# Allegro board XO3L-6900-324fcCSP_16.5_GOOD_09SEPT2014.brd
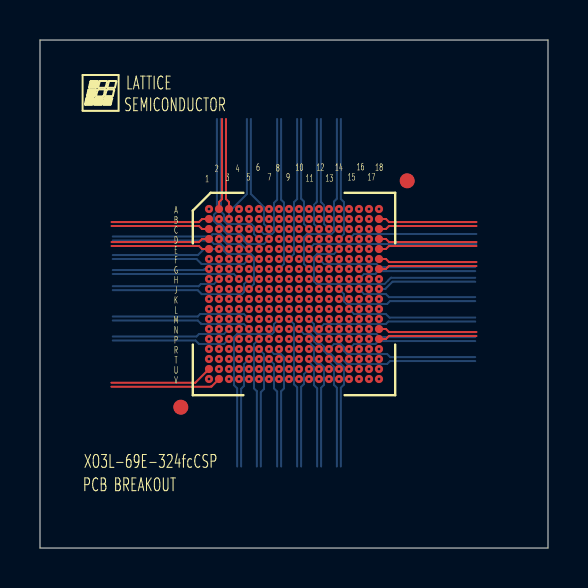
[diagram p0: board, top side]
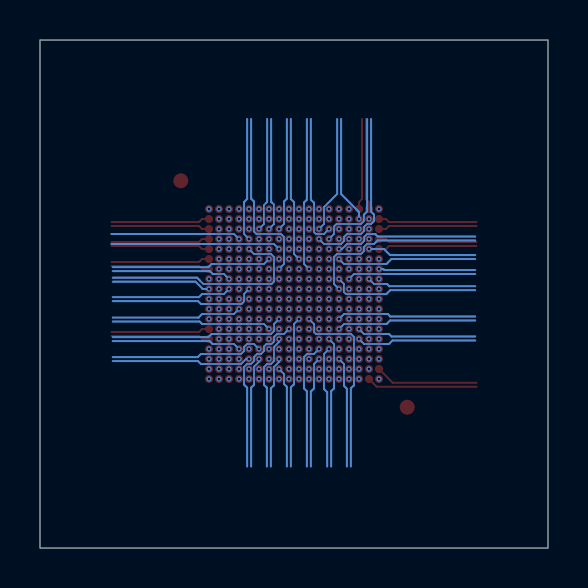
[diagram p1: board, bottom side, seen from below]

Outline 25.4 x 25.4 mm; copper layers: TOP, L2_GND, L3_SIGNAL1, L4_SIGNAL2, L5_GND, L6_SIG3, L5_PWR, BOTTOM. Coordinates in mm from the lower left corner of the outline.
Outline path: 0,25.4 25.4,25.4 25.4,0 0,0 0,25.4

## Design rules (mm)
net group CDPB4: nets PB4C PB4D
net group CDPB6: nets PB6C PB6D
net group CDPB7: nets PB7C PB7D
net group CDPB9: nets PB9C PB9D
net group CDPB13: nets PB13C PB13D
net group CDPB15: nets PB15C PB15D
net group CDPB16: nets PB16C PB16D
net group CDPB18: nets PB18C PB18D
net group CDPB21: nets PB21C PB21D
net group CDPB23: nets PB23C PB23D
net group CDPB26: nets PB26C PB26D
net group CDPB31: nets PB31C PB31D
net group CDPB35: nets PB35C PB35D
net group CDPB37: nets PB37C PB37D
net group CDPB38: nets PB38C PB38D
net group CDPL2: nets PL2C PL2D
net group CDPL3: nets PL3C PL3D
net group CDPL4: nets PL4C PL4D
net group CDPL5: nets PL5C PL5D
net group CDPL6: nets PL6C PL6D
net group CDPL7: nets PL7C PL7D
net group CDPL9: nets PL9C PL9D
net group CDPL10: nets PL10C PL10D
net group CDPL15: nets PL15C PL15D
net group CDPL16: nets PL16C PL16D
net group CDPL18: nets PL18C PL18D
net group CDPL19: nets PL19C PL19D
net group CDPL21: nets PL21C PL21D
net group CDPL23: nets PL23C PL23D
net group CDPL24: nets PL24C PL24D
net group CDPL25: nets PL25C PL25D
net group CDPR2: nets PR2C PR2D
net group CDPR3: nets PR3C PR3D
net group CDPR4: nets PR4C PR4D
net group CDPR6: nets PR6C PR6D
net group CDPR7: nets PR7C PR7D
net group CDPR8: nets PR8C PR8D
net group CDPR10: nets PR10C PR10D
net group CDPR11: nets PR11C PR11D
net group CDPR16: nets PR16C PR16D
net group CDPR17: nets PR17C PR17D
net group CDPR19: nets PR19C PR19D
net group CDPR21: nets PR21C PR21D
net group CDPR22: nets PR22C PR22D
net group CDPR23: nets PR23C PR23D
net group CDPR24: nets PR24C PR24D
net group CDPR25: nets PR25C PR25D
net group CDPT9: nets PT9C PT9D
net group CDPT10: nets PT10C PT10D
net group CDPT11: nets PT11C PT11D
net group CDPT14: nets PT14C PT14D
net group CDPT17: nets PT17C PT17D
net group CDPT18: nets PT18C PT18D
net group CDPT21: nets PT21C PT21D
net group CDPT22: nets PT22C PT22D
net group CDPT25: nets PT25C PT25D
net group CDPT26: nets PT26C PT26D
net group CDPT27: nets PT27C PT27D
net group CDPT33: nets PT33C PT33D
net group CDPT34: nets PT34C PT34D
net group CDPT35: nets PT35C PT35D
net group CDPT36: nets PT36C PT36D
net group DP1: nets PB16A PB16B
net group DP2: nets PB7A PB7B
net group DP3: nets PB13A PB13B
net group DP4: nets PB18A PB18B
net group PB4: nets PB4A PB4B
net group PB6: nets PB6A PB6B
net group PB9: nets PB9A PB9B
net group PB10: nets PB10A PB10B
net group PB12: nets PB12A PB12B
net group PB15: nets PB15A PB15B
net group PB21: nets PB21A PB21B
net group PB23: nets PB23A PB23B
net group PB26: nets PB26A PB26B
net group PB28: nets PB28A PB28B
net group PB29: nets PB29A PB29B
net group PB31: nets PB31A PB31B
net group PB32: nets PB32A PB32B
net group PB34: nets PB34A PB34B
net group PB35: nets PB35A PB35B
net group PB37: nets PB37A PB37B
net group PB38: nets PB38A PB38B
net group PL2: nets PL2A PL2B
net group PL3: nets PL3A PL3B
net group PL4: nets PL4A PL4B
net group PL5: nets PL5A PL5B
net group PL6: nets PL6A PL6B
net group PL8: nets PL8A PL8B
net group PL9: nets PL9A PL9B
net group PL10: nets PL10A PL10B
net group PL11: nets PL11A PL11B
net group PL12: nets PL12A PL12B
net group PL15: nets PL15A PL15B
net group PL17: nets PL17A PL17B
net group PL18: nets PL18A PL18B
net group PL19: nets PL19A PL19B
net group PL22: nets PL22A PL22B
net group PL23: nets PL23A PL23B
net group PL24: nets PL24A PL24B
net group PL25: nets PL25A PL25B
net group PR2: nets PR2A PR2B
net group PR3: nets PR3A PR3B
net group PR4: nets PR4A PR4B
net group PR5: nets PR5A PR5B
net group PR7: nets PR7A PR7B
net group PR8: nets PR8A PR8B
net group PR9: nets PR9A PR9B
net group PR11: nets PR11A PR11B
net group PR12: nets PR12A PR12B
net group PR15: nets PR15A PR15B
net group PR16: nets PR16A PR16B
net group PR17: nets PR17A PR17B
net group PR18: nets PR18A PR18B
net group PR21: nets PR21A PR21B
net group PR22: nets PR22A PR22B
net group PR23: nets PR23A PR23B
net group PR24: nets PR24A PR24B
net group PR25: nets PR25A PR25B
net group PT9: nets PT9A PT9B
net group PT10: nets PT10A PT10B
net group PT11: nets PT11A PT11B
net group PT12: nets PT12A PT12B
net group PT13: nets PT13A PT13B
net group PT14: nets PT14A PT14B
net group PT15: nets PT15A PT15B
net group PT16: nets PT16A PT16B
net group PT17: nets PT17A PT17B
net group PT18: nets PT18A PT18B
net group PT21: nets PT21A PT21B
net group PT22: nets PT22A PT22B
net group PT25: nets PT25A PT25B
net group PT26: nets PT26A PT26B
net group PT27: nets PT27A PT27B
net group PT28: nets PT28A PT28B
net group PT32: nets PT32A PT32B
net group PT33: nets PT33A PT33B
net group PT34: nets PT34A PT34B
net group PT35: nets PT35A PT35B
net group PT36: nets PT36A PT36B

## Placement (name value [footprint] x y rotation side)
BGA  -  [BGA324N50P18X18_1000X1000X10-1]  12.7 12.7 270 top
NOREF  -  []  1.85 21.54 0 top

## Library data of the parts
BGA = BGA324N50P18X18_1000X1000X10-1

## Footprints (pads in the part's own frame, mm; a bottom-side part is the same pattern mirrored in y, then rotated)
BGA324N50P18X18_1000X1000X10-1
  round 0.75 smd: (-5.66,5.66) (5.66,-5.66)
  round 0.406 smd: A1(-4.25,-4.25) A2(-4.25,-3.75) A3(-4.25,-3.25) A4(-4.25,-2.75) A5(-4.25,-2.25) A6(-4.25,-1.75) A7(-4.25,-1.25) A8(-4.25,-0.75) A9(-4.25,-0.25) A10(-4.25,0.25) A11(-4.25,0.75) A12(-4.25,1.25) A13(-4.25,1.75) A14(-4.25,2.25) A15(-4.25,2.75) A16(-4.25,3.25) A17(-4.25,3.75) A18(-4.25,4.25) B1(-3.75,-4.25) B2(-3.75,-3.75) B3(-3.75,-3.25) B4(-3.75,-2.75) B5(-3.75,-2.25) B6(-3.75,-1.75) B7(-3.75,-1.25) B8(-3.75,-0.75) B9(-3.75,-0.25) B10(-3.75,0.25) B11(-3.75,0.75) B12(-3.75,1.25) B13(-3.75,1.75) B14(-3.75,2.25) B15(-3.75,2.75) B16(-3.75,3.25) B17(-3.75,3.75) B18(-3.75,4.25) C1(-3.25,-4.25) C2(-3.25,-3.75) C3(-3.25,-3.25) C4(-3.25,-2.75) C5(-3.25,-2.25) C6(-3.25,-1.75) C7(-3.25,-1.25) C8(-3.25,-0.75) C9(-3.25,-0.25) C10(-3.25,0.25) C11(-3.25,0.75) C12(-3.25,1.25) C13(-3.25,1.75) C14(-3.25,2.25) C15(-3.25,2.75) C16(-3.25,3.25) C17(-3.25,3.75) C18(-3.25,4.25) D1(-2.75,-4.25) D2(-2.75,-3.75) D3(-2.75,-3.25) D4(-2.75,-2.75) D5(-2.75,-2.25) D6(-2.75,-1.75) D7(-2.75,-1.25) D8(-2.75,-0.75) D9(-2.75,-0.25) D10(-2.75,0.25) D11(-2.75,0.75) D12(-2.75,1.25) D13(-2.75,1.75) D14(-2.75,2.25) D15(-2.75,2.75) D16(-2.75,3.25) D17(-2.75,3.75) D18(-2.75,4.25) E1(-2.25,-4.25) E2(-2.25,-3.75) E3(-2.25,-3.25) E4(-2.25,-2.75) E5(-2.25,-2.25) E6(-2.25,-1.75) E7(-2.25,-1.25) E8(-2.25,-0.75) E9(-2.25,-0.25) E10(-2.25,0.25) E11(-2.25,0.75) E12(-2.25,1.25) E13(-2.25,1.75) E14(-2.25,2.25) E15(-2.25,2.75) E16(-2.25,3.25) E17(-2.25,3.75) E18(-2.25,4.25) F1(-1.75,-4.25) F2(-1.75,-3.75) F3(-1.75,-3.25) F4(-1.75,-2.75) F5(-1.75,-2.25) F6(-1.75,-1.75) F7(-1.75,-1.25) F8(-1.75,-0.75) F9(-1.75,-0.25) F10(-1.75,0.25) F11(-1.75,0.75) F12(-1.75,1.25) F13(-1.75,1.75) F14(-1.75,2.25) F15(-1.75,2.75) F16(-1.75,3.25) F17(-1.75,3.75) F18(-1.75,4.25) G1(-1.25,-4.25) G2(-1.25,-3.75) G3(-1.25,-3.25) G4(-1.25,-2.75) G5(-1.25,-2.25) G6(-1.25,-1.75) G7(-1.25,-1.25) G8(-1.25,-0.75) G9(-1.25,-0.25) G10(-1.25,0.25) G11(-1.25,0.75) G12(-1.25,1.25) G13(-1.25,1.75) G14(-1.25,2.25) G15(-1.25,2.75) G16(-1.25,3.25) G17(-1.25,3.75) G18(-1.25,4.25) H1(-0.75,-4.25) H2(-0.75,-3.75) H3(-0.75,-3.25) H4(-0.75,-2.75) H5(-0.75,-2.25) H6(-0.75,-1.75) H7(-0.75,-1.25) H8(-0.75,-0.75) H9(-0.75,-0.25) H10(-0.75,0.25) H11(-0.75,0.75) H12(-0.75,1.25) H13(-0.75,1.75) H14(-0.75,2.25) H15(-0.75,2.75) H16(-0.75,3.25) H17(-0.75,3.75) H18(-0.75,4.25) J1(-0.25,-4.25) J2(-0.25,-3.75) J3(-0.25,-3.25) J4(-0.25,-2.75) J5(-0.25,-2.25) J6(-0.25,-1.75) J7(-0.25,-1.25) J8(-0.25,-0.75) J9(-0.25,-0.25) J10(-0.25,0.25) J11(-0.25,0.75) J12(-0.25,1.25) J13(-0.25,1.75) J14(-0.25,2.25) J15(-0.25,2.75) J16(-0.25,3.25) J17(-0.25,3.75) J18(-0.25,4.25) K1(0.25,-4.25) K2(0.25,-3.75) K3(0.25,-3.25) K4(0.25,-2.75) K5(0.25,-2.25) K6(0.25,-1.75) K7(0.25,-1.25) K8(0.25,-0.75) K9(0.25,-0.25) K10(0.25,0.25) K11(0.25,0.75) K12(0.25,1.25) K13(0.25,1.75) K14(0.25,2.25) K15(0.25,2.75) K16(0.25,3.25) K17(0.25,3.75) K18(0.25,4.25) L1(0.75,-4.25) L2(0.75,-3.75) L3(0.75,-3.25) L4(0.75,-2.75) L5(0.75,-2.25) L6(0.75,-1.75) L7(0.75,-1.25) L8(0.75,-0.75) L9(0.75,-0.25) L10(0.75,0.25) L11(0.75,0.75) L12(0.75,1.25) L13(0.75,1.75) L14(0.75,2.25) L15(0.75,2.75) L16(0.75,3.25) L17(0.75,3.75) L18(0.75,4.25) M1(1.25,-4.25) M2(1.25,-3.75) M3(1.25,-3.25) M4(1.25,-2.75) M5(1.25,-2.25) M6(1.25,-1.75) M7(1.25,-1.25) M8(1.25,-0.75) M9(1.25,-0.25) M10(1.25,0.25) M11(1.25,0.75) M12(1.25,1.25) M13(1.25,1.75) M14(1.25,2.25) M15(1.25,2.75) M16(1.25,3.25) M17(1.25,3.75) M18(1.25,4.25) N1(1.75,-4.25) N2(1.75,-3.75) N3(1.75,-3.25) N4(1.75,-2.75) N5(1.75,-2.25) N6(1.75,-1.75) N7(1.75,-1.25) N8(1.75,-0.75) N9(1.75,-0.25) N10(1.75,0.25) N11(1.75,0.75) N12(1.75,1.25) N13(1.75,1.75) N14(1.75,2.25) N15(1.75,2.75) N16(1.75,3.25) N17(1.75,3.75) N18(1.75,4.25) P1(2.25,-4.25) P2(2.25,-3.75) P3(2.25,-3.25) P4(2.25,-2.75) P5(2.25,-2.25) P6(2.25,-1.75) P7(2.25,-1.25) P8(2.25,-0.75) P9(2.25,-0.25) P10(2.25,0.25) P11(2.25,0.75) P12(2.25,1.25) P13(2.25,1.75) P14(2.25,2.25) P15(2.25,2.75) P16(2.25,3.25) P17(2.25,3.75) P18(2.25,4.25) R1(2.75,-4.25) R2(2.75,-3.75) R3(2.75,-3.25) R4(2.75,-2.75) R5(2.75,-2.25) R6(2.75,-1.75) R7(2.75,-1.25) R8(2.75,-0.75) R9(2.75,-0.25) R10(2.75,0.25) R11(2.75,0.75) R12(2.75,1.25) R13(2.75,1.75) R14(2.75,2.25) R15(2.75,2.75) R16(2.75,3.25) R17(2.75,3.75) R18(2.75,4.25) T1(3.25,-4.25) T2(3.25,-3.75) T3(3.25,-3.25) T4(3.25,-2.75) T5(3.25,-2.25) T6(3.25,-1.75) T7(3.25,-1.25) T8(3.25,-0.75) T9(3.25,-0.25) T10(3.25,0.25) T11(3.25,0.75) T12(3.25,1.25) T13(3.25,1.75) T14(3.25,2.25) T15(3.25,2.75) T16(3.25,3.25) T17(3.25,3.75) T18(3.25,4.25) U1(3.75,-4.25) U2(3.75,-3.75) U3(3.75,-3.25) U4(3.75,-2.75) U5(3.75,-2.25) U6(3.75,-1.75) U7(3.75,-1.25) U8(3.75,-0.75) U9(3.75,-0.25) U10(3.75,0.25) U11(3.75,0.75) U12(3.75,1.25) U13(3.75,1.75) U14(3.75,2.25) U15(3.75,2.75) U16(3.75,3.25) U17(3.75,3.75) U18(3.75,4.25) V1(4.25,-4.25) V2(4.25,-3.75) V3(4.25,-3.25) V4(4.25,-2.75) V5(4.25,-2.25) V6(4.25,-1.75) V7(4.25,-1.25) V8(4.25,-0.75) V9(4.25,-0.25) V10(4.25,0.25) V11(4.25,0.75) V12(4.25,1.25) V13(4.25,1.75) V14(4.25,2.25) V15(4.25,2.75) V16(4.25,3.25) V17(4.25,3.75) V18(4.25,4.25)

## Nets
GND: BGA.A1 BGA.A18 BGA.F6 BGA.F13 BGA.J8 BGA.J9 BGA.J10 BGA.J11 BGA.K8 BGA.K9 BGA.K10 BGA.K11 BGA.N6 BGA.N13 BGA.V1 BGA.V18
VCC: BGA.H7 BGA.H12 BGA.J7 BGA.J12 BGA.K7 BGA.K12 BGA.L7 BGA.L12
VCCIO0: BGA.H8 BGA.H9 BGA.H10 BGA.H11
VCCIO1: BGA.H6 BGA.J6 BGA.K6 BGA.L6
VCCIO2: BGA.L8 BGA.L9 BGA.L10 BGA.L11
VCCIO3: BGA.L13 BGA.M13
VCCIO4: BGA.J13 BGA.K13
VCCIO5: BGA.G13 BGA.H13
PB4A: BGA.R15
PB4B: BGA.M11
PB4C: BGA.N11
PB4D: BGA.T15
PB6A: BGA.V17
PB6B: BGA.R14
PB6C: BGA.V16
PB6D: BGA.U16
PB7A: BGA.V14
PB7B: BGA.U14
PB7C: BGA.V15
PB7D: BGA.U15
PB9A: BGA.N10
PB9B: BGA.T13
PB9C: BGA.T14
PB9D: BGA.R13
PB10A: BGA.V13
PB10B: BGA.M10
PB12A: BGA.P13
PB12B: BGA.P12
PB13A: BGA.U13
PB13B: BGA.U12
PB13C: BGA.R12
PB13D: BGA.T12
PB15A: BGA.P11
PB15B: BGA.T11
PB15C: BGA.N9
PB15D: BGA.V12
PB16A: BGA.R11
PB16B: BGA.V11
PB16C: BGA.U11
PB16D: BGA.M9
PB18A: BGA.P10
PB18B: BGA.R10
PB18C: BGA.U10
PB18D: BGA.T10
PB21A: BGA.V10
PB21B: BGA.P9
PB21C: BGA.U9
PB21D: BGA.V9
PB23A: BGA.T9
PB23B: BGA.T8
PB23C: BGA.R9
PB23D: BGA.V8
PB26A: BGA.U8
PB26B: BGA.V7
PB26C: BGA.R8
PB26D: BGA.P8
PB28A: BGA.R7
PB28B: BGA.T7
PB29A: BGA.N8
PB29B: BGA.U7
PB31A: BGA.U6
PB31B: BGA.V6
PB31C: BGA.R6
PB31D: BGA.P6
PB32A: BGA.P7
PB32B: BGA.T6
PB34A: BGA.T5
PB34B: BGA.M8
PB35A: BGA.U5
PB35B: BGA.U4
PB35C: BGA.V5
PB35D: BGA.N7
PB37A: BGA.V4
PB37B: BGA.R5
PB37C: BGA.U3
PB37D: BGA.V3
PB38A: BGA.U2
PB38B: BGA.T4
PB38C: BGA.V2
PB38D: BGA.U1
PL2A: BGA.D16
PL2B: BGA.E15
PL2C: BGA.C17
PL2D: BGA.D17
PL3A: BGA.B18
PL3B: BGA.C18
PL3C: BGA.G12
PL3D: BGA.E17
PL4A: BGA.D18
PL4B: BGA.E18
PL4C: BGA.F15
PL4D: BGA.F14
PL5A: BGA.E16
PL5B: BGA.F16
PL5C: BGA.F17
PL5D: BGA.G14
PL6A: BGA.F18
PL6B: BGA.G18
PL6C: BGA.G15
PL6D: BGA.H14
PL7C: BGA.H17
PL7D: BGA.H15
PL8A: BGA.G16
PL8B: BGA.G17
PL9A: BGA.H16
PL9B: BGA.F12
PL9C: BGA.H18
PL9D: BGA.J15
PL10A: BGA.J14
PL10B: BGA.J16
PL10C: BGA.E14
PL10D: BGA.J18
PL11A: BGA.J17
PL11B: BGA.K18
PL12A: BGA.K17
PL12B: BGA.K15
PL15A: BGA.K16
PL15B: BGA.K14
PL15C: BGA.L17
PL15D: BGA.L14
PL16C: BGA.N12
PL16D: BGA.L15
PL17A: BGA.L18
PL17B: BGA.L16
PL18A: BGA.M16
PL18B: BGA.M18
PL18C: BGA.N14
PL18D: BGA.M17
PL19A: BGA.M15
PL19B: BGA.N17
PL19C: BGA.N16
PL19D: BGA.N15
PL21C: BGA.M14
PL21D: BGA.M12
PL22A: BGA.N18
PL22B: BGA.P18
PL23A: BGA.P15
PL23B: BGA.P16
PL23C: BGA.P17
PL23D: BGA.R17
PL24A: BGA.R16
PL24B: BGA.R18
PL24C: BGA.T17
PL24D: BGA.P14
PL25A: BGA.T18
PL25B: BGA.U17
PL25C: BGA.U18
PL25D: BGA.T16
PR2A: BGA.B1
PR2B: BGA.C1
PR2C: BGA.C3
PR2D: BGA.C2
PR3A: BGA.D1
PR3B: BGA.E1
PR3C: BGA.G7
PR3D: BGA.D3
PR4A: BGA.D2
PR4B: BGA.E4
PR4C: BGA.E3
PR4D: BGA.F3
PR5A: BGA.E2
PR5B: BGA.F5
PR6C: BGA.F4
PR6D: BGA.F2
PR7A: BGA.G6
PR7B: BGA.F1
PR7C: BGA.G5
PR7D: BGA.G3
PR8A: BGA.G4
PR8B: BGA.G2
PR8C: BGA.G1
PR8D: BGA.H4
PR9A: BGA.H5
PR9B: BGA.H2
PR10C: BGA.H3
PR10D: BGA.H1
PR11A: BGA.E5
PR11B: BGA.J5
PR11C: BGA.J4
PR11D: BGA.J1
PR12A: BGA.J3
PR12B: BGA.J2
PR15A: BGA.K1
PR15B: BGA.K2
PR16A: BGA.K3
PR16B: BGA.K5
PR16C: BGA.K4
PR16D: BGA.L3
PR17A: BGA.L1
PR17B: BGA.L2
PR17C: BGA.L5
PR17D: BGA.L4
PR18A: BGA.M1
PR18B: BGA.M6
PR19C: BGA.M3
PR19D: BGA.M4
PR21A: BGA.M2
PR21B: BGA.N1
PR21C: BGA.N2
PR21D: BGA.N4
PR22A: BGA.M5
PR22B: BGA.N5
PR22C: BGA.N3
PR22D: BGA.P3
PR23A: BGA.P2
PR23B: BGA.P1
PR23C: BGA.R1
PR23D: BGA.P4
PR24A: BGA.R2
PR24B: BGA.R3
PR24C: BGA.R4
PR24D: BGA.M7
PR25A: BGA.T1
PR25B: BGA.T2
PR25C: BGA.P5
PR25D: BGA.T3
PT9A: BGA.B16
PT9B: BGA.B17
PT9C: BGA.A17
PT9D: BGA.B15
PT10A: BGA.C16
PT10B: BGA.A15
PT10C: BGA.C14
PT10D: BGA.A16
PT11A: BGA.F11
PT11B: BGA.C15
PT11C: BGA.E13
PT11D: BGA.B14
PT12A: BGA.D13
PT12B: BGA.A14
PT12C: BGA.D15
PT13A: BGA.G11
PT13B: BGA.D14
PT14A: BGA.A13
PT14B: BGA.D12
PT14C: BGA.B13
PT14D: BGA.F10
PT15A: BGA.C13
PT15B: BGA.C12
PT16A: BGA.E12
PT16B: BGA.A12
PT16C: BGA.E11
PT17A: BGA.F9
PT17B: BGA.C11
PT17C: BGA.G10
PT17D: BGA.B12
PT18A: BGA.E10
PT18B: BGA.B11
PT18C: BGA.D11
PT18D: BGA.G9
PT21A: BGA.B10
PT21B: BGA.C10
PT21C: BGA.A11
PT21D: BGA.D10
PT22A: BGA.A10
PT22B: BGA.D9
PT22C: BGA.A9
PT22D: BGA.B9
PT25A: BGA.C9
PT25B: BGA.E9
PT25C: BGA.B8
PT25D: BGA.A8
PT26A: BGA.D8
PT26B: BGA.F8
PT26C: BGA.C8
PT26D: BGA.E8
PT27A: BGA.C7
PT27B: BGA.B3
PT27C: BGA.A7
PT27D: BGA.B7
PT28A: BGA.A6
PT28B: BGA.E7
PT32A: BGA.D7
PT32B: BGA.D6
PT33A: BGA.G8
PT33B: BGA.C6
PT33C: BGA.B5
PT33D: BGA.B6
PT34A: BGA.A4
PT34B: BGA.E6
PT34C: BGA.F7
PT34D: BGA.A5
PT35A: BGA.D4
PT35B: BGA.C5
PT35C: BGA.D5
PT35D: BGA.B2
PT36A: BGA.A3
PT36B: BGA.A2
PT36C: BGA.C4
PT36D: BGA.B4

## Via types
v1: diameter 0.254, hole 0.152, TOP to BOTTOM, 308 vias

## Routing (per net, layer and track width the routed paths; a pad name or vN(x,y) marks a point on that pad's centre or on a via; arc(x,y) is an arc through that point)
GND:
  vias: v1(8.45,16.95) v1(8.45,8.45) v1(10.95,14.45) v1(10.95,10.95) v1(11.95,12.95) v1(11.95,12.45) v1(12.45,12.95) v1(12.45,12.45) v1(12.95,12.95) v1(12.95,12.45) v1(13.45,12.95) v1(13.45,12.45) v1(14.45,14.45) v1(14.45,10.95) v1(16.95,16.95) v1(16.95,8.45)
VCC:
  vias: v1(11.45,13.45) v1(11.45,12.95) v1(11.45,12.45) v1(11.45,11.95) v1(13.95,13.45) v1(13.95,12.95) v1(13.95,12.45) v1(13.95,11.95)
VCCIO0:
  vias: v1(11.95,13.45) v1(12.45,13.45) v1(12.95,13.45) v1(13.45,13.45)
VCCIO1:
  vias: v1(10.95,13.45) v1(10.95,12.95) v1(10.95,12.45) v1(10.95,11.95)
VCCIO2:
  vias: v1(11.95,11.95) v1(12.45,11.95) v1(12.95,11.95) v1(13.45,11.95)
VCCIO3:
  vias: v1(14.45,11.95) v1(14.45,11.45)
VCCIO4:
  vias: v1(14.45,12.95) v1(14.45,12.45)
VCCIO5:
  vias: v1(14.45,13.95) v1(14.45,13.45)
PB4A: length 6.5
  BOTTOM w0.089: v1(15.45,9.95) 15.7,10.2 16.64,10.2
  BOTTOM w0.102: 16.64,10.2 16.77,10.2 16.92,10.35 21.76,10.35
PB4B: length 8.9
  BOTTOM w0.089: 16.51,10.7 13.85,10.7 13.7,10.85 13.7,11.2 v1(13.45,11.45)
  BOTTOM w0.102: 16.51,10.7 16.82,10.7 16.98,10.54 21.76,10.54
PB4C: length 8.4
  L6_SIG3 w0.089: 14.7,8.29 14.7,9.05 14.55,9.2 13.33,9.2 13.2,9.33 13.2,10.7 v1(13.45,10.95)
  L6_SIG3 w0.102: 14.7,8.29 14.7,8.14 14.82,8.01 14.82,4.08
PB4D: length 5.5
  L6_SIG3 w0.089: 15.2,8.26 15.2,9.2 15.45,9.45 v1(15.45,9.45)
  L6_SIG3 w0.102: 15.02,4.08 15.02,8.04 15.2,8.22 15.2,8.26
PB6A: length 4.5
  L3_SIGNAL1 w0.102: v1(16.45,8.45) 16.45,8.2 16.76,7.89 16.76,4.08
PB6B: length 7
  L3_SIGNAL1 w0.089: 16.2,8.26 16.2,9.05 16.05,9.2 15.35,9.2 15.2,9.35 15.2,9.7 v1(14.95,9.95)
  L3_SIGNAL1 w0.102: 16.2,8.26 16.2,8.17 16.37,7.99 16.38,7.99 16.56,7.81 16.56,4.08
PB6C: length 4.4
  L3_SIGNAL1 w0.102: v1(15.95,8.45) 15.9,8.4 15.9,8.08 16.02,7.95 16.02,4.08
PB6D: length 5
  L3_SIGNAL1 w0.089: v1(15.95,8.95) 15.7,8.7 15.7,8.23
  L3_SIGNAL1 w0.102: 15.7,8.23 15.7,7.99 15.82,7.87 15.82,4.08
PB7A: length 4.5
  L4_SIGNAL2 w0.102: 15.26,4.08 15.26,7.69 14.95,8 v1(14.95,8.45)
PB7B: length 5.1
  L4_SIGNAL2 w0.089: v1(14.95,8.95) 15.2,8.7 15.2,8.33
  L4_SIGNAL2 w0.102: 15.46,4.08 15.46,7.78 15.2,8.03 15.2,8.33
PB7C: length 4.5
  L3_SIGNAL1 w0.102: v1(15.45,8.45) 15.4,8.4 15.4,8.12 15.1,7.82 15.1,4.08
PB7D: length 5.1
  L3_SIGNAL1 w0.089: v1(15.45,8.95) 15.2,8.7 15.2,8.42
  L3_SIGNAL1 w0.102: 14.9,4.08 14.9,7.9 15.2,8.2 15.2,8.42
PB9A: length 8.5
  BOTTOM w0.089: 15.2,8.29 15.2,9.05 15.05,9.2 14.85,9.2 14.7,9.35 14.7,9.55 14.55,9.7 14.35,9.7 14.2,9.85 14.2,10.08 14.08,10.2 13.83,10.2 13.7,10.33 13.7,10.55 13.55,10.7 13.2,10.7 v1(12.95,10.95)
  BOTTOM w0.102: 15.2,8.29 15.2,8.17 15.04,8.01 15.04,4.08
PB9B: length 5.5
  BOTTOM w0.089: v1(14.45,9.45) 14.45,9.32 14.7,9.07 14.7,8.23
  BOTTOM w0.102: 14.7,8.23 14.7,8.16 14.85,8.01 14.85,4.08
PB9C: length 7
  BOTTOM w0.089: v1(14.95,9.45) 15.1,9.45 15.35,9.2 17.07,9.2
  BOTTOM w0.102: 21.76,9.35 17.5,9.35 17.35,9.2 17.07,9.2
PB9D: length 7.8
  BOTTOM w0.089: 17.14,9.7 15.35,9.7 15.2,9.85 15.2,10.05 15.05,10.2 14.7,10.2 v1(14.45,9.95)
  BOTTOM w0.102: 17.14,9.7 17.36,9.7 17.51,9.54 21.76,9.54
PB10A: length 4.4
  L4_SIGNAL2 w0.102: 14.63,4.08 14.63,7.66 14.5,7.79 14.5,8.15 14.45,8.2 v1(14.45,8.45)
PB10B: length 8.9
  L4_SIGNAL2 w0.089: 14.7,8.35 14.7,11.06 14.56,11.2 13.2,11.2 v1(12.95,11.45)
  L4_SIGNAL2 w0.102: 14.82,4.08 14.82,7.74 14.7,7.87 14.7,8.35
PB12A: length 7.5
  L6_SIG3 w0.089: 16.66,10.63 16.58,10.7 14.7,10.7 v1(14.45,10.45)
  L6_SIG3 w0.102: 21.82,10.55 16.73,10.55 16.66,10.63
PB12B: length 8
  L6_SIG3 w0.089: v1(13.95,10.45) 14.2,10.2 16.67,10.2 16.73,10.26
  L6_SIG3 w0.102: 16.73,10.26 16.82,10.36 21.82,10.36
PB13A: length 5
  L6_SIG3 w0.089: v1(14.45,8.95) 14.2,8.7 14.2,8.39
  L6_SIG3 w0.102: 14.2,8.39 14.2,8.23 14.05,8.09 14.05,4.08
PB13B: length 5
  L6_SIG3 w0.089: v1(13.95,8.95) 13.82,8.82 13.82,8.81 13.7,8.69 13.7,8.39
  L6_SIG3 w0.102: 13.7,8.39 13.7,8.22 13.86,8.06 13.86,4.08
PB13C: length 6.5
  L3_SIGNAL1 w0.089: 14.7,8.33 14.7,9.55 14.55,9.7 14.35,9.7 14.2,9.7 v1(13.95,9.95)
  L3_SIGNAL1 w0.102: 14.51,4.08 14.51,7.98 14.7,8.17 14.7,8.33
PB13D: length 5.5
  L3_SIGNAL1 w0.089: 14.2,8.26 14.2,9.2 v1(13.95,9.45)
  L3_SIGNAL1 w0.102: 14.2,8.26 14.2,8.14 14.31,8.02 14.31,4.08
PB15A: length 6.9
  BOTTOM w0.089: 14.2,8.35 14.2,8.52 14.2,9.05 14.05,9.2 13.85,9.2 13.7,9.35 13.7,10.05 13.45,10.3 v1(13.45,10.45)
  BOTTOM w0.102: 14.05,4.08 14.05,8.01 14.2,8.16 14.2,8.35
PB15B: length 5.5
  BOTTOM w0.089: v1(13.45,9.45) 13.45,9.3 13.7,9.05 13.7,8.3
  BOTTOM w0.102: 13.86,4.08 13.86,7.98 13.7,8.14 13.7,8.3
PB15C: length 8.4
  L4_SIGNAL2 w0.089: 14.2,8.55 14.2,10.01 14.2,10.56 14.06,10.7 12.7,10.7 v1(12.45,10.95)
  L4_SIGNAL2 w0.102: 14.21,4.08 14.21,7.95 14.2,7.96 14.2,8.35 14.2,8.55
PB15D: length 4.4
  L4_SIGNAL2 w0.102: 14.01,4.08 14.01,7.86 13.95,7.93 v1(13.95,8.45)
PB16A: length 6
  L4_SIGNAL2 w0.089: 13.71,7.96 13.7,7.96 13.7,9.7 v1(13.45,9.95)
  L4_SIGNAL2 w0.102: 13.71,4.08 13.71,7.96
PB16B: length 4.4
  L4_SIGNAL2 w0.102: v1(13.45,8.45) 13.45,8.01 13.51,7.96 13.51,4.08
PB16C: length 5
  BOTTOM w0.089: v1(13.45,8.95) 13.2,8.7 13.2,8.36
  BOTTOM w0.102: 13.2,8.36 13.2,8.2 13.05,8.06 13.05,4.08
PB16D: length 7.5
  BOTTOM w0.089: 12.7,8.29 12.7,11.2 v1(12.45,11.45)
  BOTTOM w0.102: 12.86,4.08 12.86,8.03 12.7,8.19 12.7,8.29
PB18A: length 7
  L3_SIGNAL1 w0.089: v1(12.95,10.45) 13.2,10.2 13.55,10.2 13.7,10.05 13.7,8.33
  L3_SIGNAL1 w0.102: 13.52,4.08 13.52,7.99 13.7,8.17 13.7,8.33
PB18B: length 6
  L3_SIGNAL1 w0.089: v1(12.95,9.95) 13.2,9.7 13.2,8.36
  L3_SIGNAL1 w0.102: 13.2,8.36 13.2,8.11 13.32,7.98 13.32,4.08
PB18C: length 5
  L6_SIG3 w0.089: 13.2,8.36 13.2,8.7 v1(12.95,8.95)
  L6_SIG3 w0.102: 13.2,8.36 13.2,8.14 13.05,7.99 13.05,4.08
PB18D: length 5.5
  L6_SIG3 w0.089: v1(12.95,9.45) 12.7,9.2 12.7,8.36
  L6_SIG3 w0.102: 12.7,8.36 12.7,8.11 12.86,7.95 12.86,4.08
PB21A: length 4.4
  L4_SIGNAL2 w0.102: 13,4.08 13,7.96 12.95,8.01 v1(12.95,8.45)
PB21B: length 6.9
  L4_SIGNAL2 w0.089: v1(12.45,10.45) 12.7,10.2 13.05,10.2 13.2,10.05 13.2,8.26
  L4_SIGNAL2 w0.102: 13.2,4.08 13.2,8.26
PB21C: length 5
  L4_SIGNAL2 w0.089: 12.71,8.14 12.71,8.69 v1(12.45,8.95)
  L4_SIGNAL2 w0.102: 12.71,4.08 12.71,8.14
PB21D: length 4.4
  L4_SIGNAL2 w0.102: v1(12.45,8.45) 12.45,8.01 12.51,7.96 12.51,4.08
PB23A: length 5.5
  L6_SIG3 w0.089: 12.2,8.23 12.2,9.2 v1(12.45,9.45)
  L6_SIG3 w0.102: 12.2,8.23 12.2,8.08 12.05,7.93 12.05,4.08
PB23B: length 5.5
  L6_SIG3 w0.089: 11.7,8.26 11.7,9.2 v1(11.95,9.45)
  L6_SIG3 w0.102: 11.7,8.26 11.7,8.11 11.86,7.95 11.86,4.08
PB23C: length 6
  L4_SIGNAL2 w0.089: 12.2,8.24 12.2,9.7 v1(12.45,9.95)
  L4_SIGNAL2 w0.102: 12.2,4.08 12.2,8.24
PB23D: length 4.4
  L4_SIGNAL2 w0.102: 12,4.08 12,7.95 11.95,8 v1(11.95,8.45)
PB26A: length 5
  L3_SIGNAL1 w0.089: 11.71,8.21 11.71,8.71 v1(11.95,8.95)
  L3_SIGNAL1 w0.102: 11.7,4.08 11.7,5.04 11.71,5.04 11.71,8.21
PB26B: length 4.4
  L3_SIGNAL1 w0.102: 11.5,4.08 11.5,5.04 11.5,5.04 11.5,8.12 11.45,8.17 v1(11.45,8.45)
PB26C: length 6.1
  L3_SIGNAL1 w0.089: v1(11.95,9.95) 12.2,9.7 12.2,8.33
  L3_SIGNAL1 w0.102: 12.38,4.08 12.38,7.93 12.2,8.11 12.2,8.33
PB26D: length 6.9
  L3_SIGNAL1 w0.089: 12.7,8.39 12.7,10.05 12.55,10.2 12.2,10.2 v1(11.95,10.45)
  L3_SIGNAL1 w0.102: 12.58,4.08 12.58,7.98 12.7,8.11 12.7,8.39
PB28A: length 6.5
  BOTTOM w0.089: v1(11.45,9.95) 11.7,9.7 12.05,9.7 12.2,9.55 12.2,8.36
  BOTTOM w0.102: 12.2,8.36 12.2,7.98 12.05,7.84 12.05,4.08
PB28B: length 5.5
  BOTTOM w0.089: 11.7,8.33 11.7,9.2 v1(11.45,9.45)
  BOTTOM w0.102: 11.7,8.33 11.7,7.98 11.86,7.83 11.86,4.08
PB29A: length 7.8
  L6_SIG3 w0.089: v1(11.95,10.95) 11.7,10.7 11.35,10.7 11.2,10.55 11.2,9.35 11.05,9.2 10.85,9.2 10.7,9.05 10.7,8.36
  L6_SIG3 w0.102: 10.7,8.36 10.7,8.17 10.85,8.02 10.85,4.08
PB29B: length 5
  L6_SIG3 w0.089: 11.2,8.35 11.2,8.7 v1(11.45,8.95)
  L6_SIG3 w0.102: 11.2,8.35 11.2,8.23 11.04,8.08 11.04,4.08
PB31A: length 5
  L3_SIGNAL1 w0.089: v1(10.95,8.95) 11.21,8.69 11.21,8.24
  L3_SIGNAL1 w0.102: 11.21,8.24 11.21,8.17 11.13,8.09 11.13,4.08
PB31B: length 4.4
  L3_SIGNAL1 w0.102: 10.93,4.08 10.93,8.17 11,8.24 11,8.4 v1(10.95,8.45)
PB31C: length 6
  BOTTOM w0.089: 11.2,8.3 11.2,9.7 v1(10.95,9.95)
  BOTTOM w0.102: 11.04,4.08 11.04,7.79 11.2,7.95 11.2,8.3
PB31D: length 6.5
  BOTTOM w0.089: v1(10.95,10.45) 10.7,10.2 10.7,8.29
  BOTTOM w0.102: 10.7,8.29 10.7,7.98 10.84,7.84 10.84,4.08
PB32A: length 6.5
  L4_SIGNAL2 w0.089: v1(11.45,10.45) 11.7,10.2 11.7,8.38
  L4_SIGNAL2 w0.102: 11.52,4.08 11.52,8.08 11.7,8.25 11.7,8.38
PB32B: length 5.5
  L4_SIGNAL2 w0.089: 11.2,8.36 11.2,9.2 v1(10.95,9.45)
  L4_SIGNAL2 w0.102: 11.2,8.36 11.2,8.2 11.33,8.08 11.33,4.08
PB34A: length 5.5
  BOTTOM w0.089: v1(10.45,9.45) 10.2,9.2 10.2,9.05 10.2,8.55 10.2,8.33
  BOTTOM w0.102: 10.06,4.08 10.06,7.96 10.2,8.11 10.2,8.33
PB34B: length 9.4
  BOTTOM w0.089: 9.7,8.35 9.7,10.55 9.85,10.7 11.61,10.7 11.69,10.79 11.69,11.19 v1(11.95,11.45)
  BOTTOM w0.102: 9.7,8.35 9.7,8.14 9.86,7.98 9.86,4.08
PB35A: length 5
  L4_SIGNAL2 w0.089: 10.7,8.33 10.7,8.7 v1(10.45,8.95)
  L4_SIGNAL2 w0.102: 10.7,8.33 10.7,8.14 10.55,7.99 10.55,4.08
PB35B: length 5
  L4_SIGNAL2 w0.089: v1(9.95,8.95) 10.2,8.7 10.2,8.29
  L4_SIGNAL2 w0.102: 10.36,4.08 10.36,8 10.2,8.15 10.2,8.29
PB35C: length 4.4
  L3_SIGNAL1 w0.102: 10.33,4.08 10.33,7.93 10.45,8.06 v1(10.45,8.45)
PB35D: length 7.5
  L3_SIGNAL1 w0.089: v1(11.45,10.95) 11.3,10.8 11.29,10.8 11.2,10.7 10.85,10.7 10.7,10.55 10.7,10.35 10.7,9.85 10.7,9.35 10.7,8.85 10.7,8.55
  L3_SIGNAL1 w0.102: 10.52,4.08 10.52,7.85 10.7,8.03 10.7,8.35 10.7,8.55
PB37A: length 4.4
  L4_SIGNAL2 w0.102: v1(9.95,8.45) 9.95,8.14 9.9,8.09 9.9,4.09
PB37B: length 6.4
  L4_SIGNAL2 w0.089: v1(10.45,9.95) 10.19,9.69 9.85,9.69 9.7,9.54 9.7,8.26
  L4_SIGNAL2 w0.102: 9.7,4.09 9.7,8.26
PB37C: length 5.1
  L3_SIGNAL1 w0.102: v1(9.45,8.95) 9.2,8.7 9.2,7.98 8.9,7.69 8.9,4.08
PB37D: length 4.5
  L3_SIGNAL1 w0.102: v1(9.45,8.45) 9.45,7.95 9.1,7.61 9.1,4.08
PB38A: length 5.9
  L3_SIGNAL1 w0.089: 9.7,8.36 9.7,8.85 9.7,9.06 9.56,9.2 9.2,9.2 v1(8.95,8.95)
  L3_SIGNAL1 w0.102: 9.7,8.36 9.7,8.08 9.81,7.96 9.81,4.08
PB38B: length 5.6
  L3_SIGNAL1 w0.089: 10.2,8.29 10.2,9.2 v1(9.95,9.45)
  L3_SIGNAL1 w0.102: 10.2,8.29 10.2,8.17 10.01,7.98 10.01,4.08
PB38C: length 5.5
  TOP w0.102: BGA.V2 8.57,8.07 3.58,8.07
PB38D: length 5.2
  TOP w0.102: 3.58,8.26 7.76,8.26 BGA.U1
PL2A: length 6
  L6_SIG3 w0.089: 16.73,15.64 16.67,15.7 16.2,15.7 v1(15.95,15.45)
  L6_SIG3 w0.102: 16.73,15.64 16.79,15.58 21.82,15.58
PL2B: length 6.5
  L6_SIG3 w0.089: v1(15.45,14.95) 15.6,14.95 15.85,15.2 15.95,15.2 16.54,15.2 16.55,15.21 16.67,15.32
  L6_SIG3 w0.102: 16.67,15.32 16.72,15.38 21.82,15.38
PL2C: length 5.4
  L3_SIGNAL1 w0.102: v1(16.45,15.95) 16.6,15.8 21.82,15.8
PL2D: length 5.4
  L3_SIGNAL1 w0.102: v1(16.45,15.45) 16.6,15.6 21.82,15.6
PL3A: length 4.9
  TOP w0.102: 21.82,16.3 17.45,16.3 17.3,16.45 BGA.B18
PL3B: length 4.9
  TOP w0.102: BGA.C18 17.3,15.95 17.45,16.1 21.82,16.1
PL3C: length 8.4
  L6_SIG3 w0.089: v1(13.95,13.95) 14.2,14.2 14.55,14.2 14.7,14.35 14.7,14.57 14.83,14.7 16.64,14.7
  L6_SIG3 w0.102: 21.82,14.81 16.91,14.81 16.79,14.7 16.64,14.7
PL3D: length 5.4
  L6_SIG3 w0.102: 21.82,15.01 16.82,15.01 16.76,14.95 v1(16.45,14.95)
PL4A: length 4.9
  TOP w0.102: 21.82,15.3 17.45,15.3 17.3,15.45 BGA.D18
PL4B: length 4.9
  TOP w0.102: BGA.E18 17.3,14.95 17.45,15.1 21.82,15.1
PL4C: length 6.5
  L4_SIGNAL2 w0.089: v1(15.45,14.45) 15.7,14.7 16.61,14.7
  L4_SIGNAL2 w0.102: 16.61,14.7 16.79,14.7 16.92,14.82 21.82,14.82
PL4D: length 7.5
  L4_SIGNAL2 w0.089: 16.61,15.2 15.35,15.2 15.2,15.05 15.2,14.7 v1(14.95,14.45)
  L4_SIGNAL2 w0.102: 16.61,15.2 16.76,15.2 16.94,15.02 21.82,15.02
PL5A: length 6
  L3_SIGNAL1 w0.089: v1(15.95,14.95) 16.2,15.2 16.64,15.2
  L3_SIGNAL1 w0.102: 16.64,15.2 16.84,15.2 17.02,15.02 21.82,15.02
PL5B: length 6
  L3_SIGNAL1 w0.089: 16.67,14.7 16.2,14.7 v1(15.95,14.45)
  L3_SIGNAL1 w0.102: 21.82,14.82 17.01,14.82 16.89,14.7 16.67,14.7
PL5C: length 5.4
  L6_SIG3 w0.102: v1(16.45,14.45) 17.07,14.45 17.2,14.32 21.82,14.32
PL5D: length 7
  L6_SIG3 w0.089: 16.67,14.2 15.2,14.2 v1(14.95,13.95)
  L6_SIG3 w0.102: 16.67,14.2 17.04,14.2 17.12,14.13 21.82,14.13
PL6A: length 4.9
  TOP w0.102: 21.82,14.3 17.45,14.3 17.3,14.45 BGA.F18
PL6B: length 4.9
  TOP w0.102: BGA.G18 17.3,13.95 17.45,14.1 21.82,14.1
PL6C: length 6.5
  L4_SIGNAL2 w0.089: v1(15.45,13.95) 15.7,14.2 16.67,14.2
  L4_SIGNAL2 w0.102: 21.82,14.09 16.86,14.09 16.75,14.2 16.67,14.2
PL6D: length 7.1
  L4_SIGNAL2 w0.089: v1(14.95,13.45) 15.2,13.7 16.63,13.7 16.76,13.83
  L4_SIGNAL2 w0.102: 21.82,13.89 16.82,13.89 16.76,13.83
PL7C: length 5.5
  L3_SIGNAL1 w0.102: 21.82,13.59 17.38,13.59 17.26,13.7 16.7,13.7 v1(16.45,13.45)
PL7D: length 6.6
  L3_SIGNAL1 w0.089: v1(15.45,13.45) 15.7,13.2 17.11,13.2
  L3_SIGNAL1 w0.102: 17.11,13.2 17.2,13.2 17.39,13.39 21.82,13.39
PL8A: length 6.1
  L3_SIGNAL1 w0.089: 16.7,14.2 16.2,14.2 v1(15.95,13.95)
  L3_SIGNAL1 w0.102: 16.7,14.2 17.05,14.2 17.36,14.5 21.82,14.5
PL8B: length 5.5
  L3_SIGNAL1 w0.102: v1(16.45,13.95) 17.08,13.95 17.44,14.3 21.82,14.3
PL9A: length 6
  BOTTOM w0.089: v1(15.95,13.45) 16.2,13.7 16.61,13.7
  BOTTOM w0.102: 16.61,13.7 16.76,13.7 16.91,13.85 21.76,13.85
PL9B: length 8
  BOTTOM w0.089: 16.68,14.2 14.2,14.2 v1(13.95,14.45)
  BOTTOM w0.102: 21.76,14.04 16.98,14.04 16.82,14.2 16.68,14.2
PL9C: length 5
  L6_SIG3 w0.102: v1(16.95,13.45) 16.95,13.45 17.14,13.64 21.82,13.64
PL9D: length 6.9
  L6_SIG3 w0.089: 16.78,13.75 16.73,13.7 15.85,13.7 15.7,13.55 15.7,13.2 v1(15.45,12.95)
  L6_SIG3 w0.102: 21.82,13.84 16.87,13.84 16.78,13.75
PL10A: length 7.4
  BOTTOM w0.089: 17.07,12.2 15.32,12.2 15.2,12.33 15.2,12.7 v1(14.95,12.95)
  BOTTOM w0.102: 21.76,12.35 17.5,12.35 17.36,12.2 17.07,12.2
PL10B: length 6
  BOTTOM w0.089: v1(15.95,12.95) 16.2,12.7 17.11,12.7
  BOTTOM w0.102: 17.11,12.7 17.29,12.7 17.45,12.54 21.76,12.54
PL10C: length 10.9
  BOTTOM w0.089: v1(14.95,14.95) 14.7,14.7 13.85,14.7 13.7,14.55 13.7,13.32 13.82,13.2 17.23,13.2 17.4,13.37
  BOTTOM w0.102: 21.76,13.51 17.54,13.51 17.4,13.37
PL10D: length 5
  BOTTOM w0.102: 21.76,13.31 17.63,13.31 17.26,12.95 v1(16.95,12.95)
PL11A: length 5.5
  L3_SIGNAL1 w0.089: v1(16.45,12.95) 16.7,12.7 17.51,12.7
  L3_SIGNAL1 w0.102: 21.82,12.7 17.51,12.7
PL11B: length 4.9
  L3_SIGNAL1 w0.102: v1(16.95,12.45) 17.43,12.45 17.48,12.5 21.82,12.5
PL12A: length 5.5
  L6_SIG3 w0.089: v1(16.45,12.45) 16.69,12.69 17.19,12.69 17.25,12.75
  L6_SIG3 w0.102: 21.82,12.82 17.32,12.82 17.25,12.75
PL12B: length 6.9
  L6_SIG3 w0.089: v1(15.45,12.45) 15.7,12.7 16.05,12.7 16.2,12.85 16.2,13.05 16.35,13.2 17.15,13.2 17.24,13.11
  L6_SIG3 w0.102: 17.24,13.11 17.32,13.02 21.82,13.02
PL15A: length 6
  L4_SIGNAL2 w0.089: 17.14,12.7 16.2,12.7 v1(15.95,12.45)
  L4_SIGNAL2 w0.102: 21.82,12.86 17.48,12.86 17.32,12.7 17.14,12.7
PL15B: length 7.4
  L4_SIGNAL2 w0.089: 17.17,13.2 15.35,13.2 15.2,13.05 15.2,12.7 v1(14.95,12.45)
  L4_SIGNAL2 w0.102: 17.17,13.2 17.39,13.2 17.53,13.06 21.82,13.06
PL15C: length 5.5
  L6_SIG3 w0.089: 17.2,12.14 17.13,12.21 16.71,12.21 v1(16.45,11.95)
  L6_SIG3 w0.102: 21.82,12.04 17.29,12.04 17.2,12.14
PL15D: length 7
  L6_SIG3 w0.089: 17.07,11.7 15.2,11.7 v1(14.95,11.95)
  L6_SIG3 w0.102: 21.82,11.85 17.34,11.85 17.2,11.7 17.07,11.7
PL16C: length 8
  BOTTOM w0.089: v1(13.95,10.95) 14.2,11.2 14.55,11.2 15.05,11.2 15.55,11.2 17.14,11.2
  BOTTOM w0.102: 21.76,11.32 17.41,11.32 17.29,11.2 17.14,11.2
PL16D: length 6.5
  BOTTOM w0.089: 17.17,11.7 15.7,11.7 v1(15.45,11.95)
  BOTTOM w0.102: 21.76,11.52 17.47,11.52 17.29,11.7 17.17,11.7
PL17A: length 4.9
  L3_SIGNAL1 w0.102: v1(16.95,11.95) 17.26,11.95 17.31,12 21.82,12
PL17B: length 6
  L3_SIGNAL1 w0.089: 17.13,12.2 16.2,12.2 v1(15.95,11.95)
  L3_SIGNAL1 w0.102: 21.82,12.2 17.13,12.2
PL18A: length 6
  L3_SIGNAL1 w0.089: 17.05,11.71 16.21,11.71 v1(15.95,11.45)
  L3_SIGNAL1 w0.102: 21.82,11.71 17.05,11.71
PL18B: length 4.9
  L3_SIGNAL1 w0.102: 21.82,11.51 17.39,11.51 17.34,11.45 v1(16.95,11.45)
PL18C: length 7.1
  L6_SIG3 w0.089: v1(14.95,10.95) 15.2,11.2 16.39,11.2 16.39,11.2 16.55,11.2 16.87,10.89
  L6_SIG3 w0.102: 21.82,10.89 16.87,10.89
PL18D: length 5.5
  L6_SIG3 w0.089: v1(16.45,11.45) 16.58,11.45 16.95,11.09
  L6_SIG3 w0.102: 21.82,11.09 16.95,11.09
PL19A: length 6.5
  L3_SIGNAL1 w0.089: v1(15.45,11.45) 15.7,11.2 16.64,11.2
  L3_SIGNAL1 w0.102: 16.64,11.2 16.82,11.2 17,11.02 21.82,11.02
PL19B: length 5.4
  L3_SIGNAL1 w0.102: 21.82,10.83 16.92,10.83 16.79,10.95 v1(16.45,10.95)
PL19C: length 6
  L4_SIGNAL2 w0.089: 16.76,11.2 16.2,11.2 v1(15.95,10.95)
  L4_SIGNAL2 w0.102: 16.76,11.2 16.93,11.03 21.82,11.03
PL19D: length 6.5
  L4_SIGNAL2 w0.089: v1(15.45,10.95) 15.7,10.7 16.66,10.7
  L4_SIGNAL2 w0.102: 21.82,10.83 16.96,10.83 16.82,10.7 16.66,10.7
PL21C: length 7
  L4_SIGNAL2 w0.089: 17.14,11.7 15.2,11.7 v1(14.95,11.45)
  L4_SIGNAL2 w0.102: 21.82,11.85 17.41,11.85 17.26,11.7 17.14,11.7
PL21D: length 8.5
  L4_SIGNAL2 w0.089: v1(13.95,11.45) 14.2,11.7 14.2,12.05 14.35,12.2 17.1,12.2
  L4_SIGNAL2 w0.102: 17.1,12.2 17.32,12.2 17.48,12.05 21.82,12.05
PL22A: length 4.9
  TOP w0.102: 21.82,10.8 17.45,10.8 17.3,10.95 BGA.N18
PL22B: length 4.9
  TOP w0.102: BGA.P18 17.3,10.45 17.45,10.6 21.82,10.6
PL23A: length 6.5
  L3_SIGNAL1 w0.089: 16.64,10.2 15.7,10.2 v1(15.45,10.45)
  L3_SIGNAL1 w0.102: 16.64,10.2 16.73,10.2 16.88,10.35 21.82,10.35
PL23B: length 6
  L3_SIGNAL1 w0.089: 16.54,10.7 16.2,10.7 v1(15.95,10.45)
  L3_SIGNAL1 w0.102: 16.54,10.7 16.67,10.7 16.82,10.54 21.82,10.54
PL23C: length 5.5
  L4_SIGNAL2 w0.102: 21.82,10.55 17.1,10.55 16.95,10.4 16.5,10.4 v1(16.45,10.45)
PL23D: length 5.5
  L4_SIGNAL2 w0.102: v1(16.45,9.95) 16.7,10.2 17.03,10.2 17.18,10.35 21.82,10.35
PL24A: length 6
  L3_SIGNAL1 w0.089: v1(15.95,9.95) 16.19,9.71 17.26,9.71
  L3_SIGNAL1 w0.102: 21.82,9.71 17.26,9.71
PL24B: length 4.9
  L3_SIGNAL1 w0.102: 21.82,9.9 17.31,9.9 17.26,9.95 v1(16.95,9.95)
PL24C: length 5.5
  L4_SIGNAL2 w0.089: 16.2,8.36 16.2,9.2 v1(16.45,9.45)
  L4_SIGNAL2 w0.102: 16.2,8.36 16.2,8.25 16.05,8.1 16.05,4.08
PL24D: length 6.9
  L4_SIGNAL2 w0.089: 15.7,8.39 15.7,10.04 15.54,10.21 15.19,10.21 v1(14.95,10.45)
  L4_SIGNAL2 w0.102: 15.86,4.08 15.86,8.08 15.7,8.23 15.7,8.39
PL25A: length 5
  L3_SIGNAL1 w0.102: v1(16.95,9.45) 17.3,9.1 21.82,9.1
PL25B: length 5.6
  L3_SIGNAL1 w0.089: v1(16.45,8.95) 16.7,8.7 17.13,8.7 17.21,8.78
  L3_SIGNAL1 w0.102: 17.21,8.78 17.33,8.9 21.82,8.9
PL25C: length 5
  L4_SIGNAL2 w0.102: v1(16.95,8.95) 17.31,9.31 21.82,9.31
PL25D: length 6.1
  L4_SIGNAL2 w0.089: v1(15.95,9.45) 16.2,9.7 17.07,9.7
  L4_SIGNAL2 w0.102: 17.07,9.7 17.2,9.7 17.39,9.51 21.82,9.51
PR2A: length 4.9
  TOP w0.102: 3.58,16.3 7.95,16.3 8.1,16.45 BGA.B1
PR2B: length 4.9
  TOP w0.102: 3.58,16.1 7.95,16.1 8.1,15.95 BGA.C1
PR2C: length 6.1
  L3_SIGNAL1 w0.089: v1(9.45,15.95) 9.2,16.2 8.76,16.2
  L3_SIGNAL1 w0.102: 3.58,16.44 8.05,16.44 8.06,16.46 8.23,16.46 8.48,16.2 8.76,16.2
PR2D: length 5.5
  L3_SIGNAL1 w0.102: 3.58,16.24 8.13,16.24 8.14,16.26 8.45,15.95 v1(8.95,15.95)
PR3A: length 4.9
  TOP w0.102: BGA.D1 8.1,15.45 7.95,15.3 3.58,15.3
PR3B: length 4.9
  TOP w0.102: 3.58,15.1 7.95,15.1 8.1,14.95 BGA.E1
PR3C: length 8.4
  L4_SIGNAL2 w0.089: v1(11.45,13.95) 11.2,14.2 11.2,14.55 11.05,14.7 8.83,14.7
  L4_SIGNAL2 w0.102: 8.83,14.7 8.67,14.7 8.49,14.88 3.64,14.88
PR3D: length 6
  L4_SIGNAL2 w0.089: v1(9.45,15.45) 9.2,15.2 8.7,15.2 8.65,15.15
  L4_SIGNAL2 w0.102: 8.65,15.15 8.58,15.07 3.64,15.07
PR4A: length 5.4
  L3_SIGNAL1 w0.089: v1(8.95,15.45) 8.58,15.45 8.53,15.51 3.58,15.51
PR4B: length 6.8
  L3_SIGNAL1 w0.089: 3.58,15.69 8.61,15.69 ; v1(9.95,14.95) 9.7,15.2 9.35,15.2 9.2,15.35 9.2,15.55 9.05,15.7 8.7,15.7
  L3_SIGNAL1 w0.102: 8.61,15.69 8.62,15.7 8.7,15.7
PR4C: length 6
  L6_SIG3 w0.089: v1(9.45,14.95) 9.2,15.2 8.73,15.2
  L6_SIG3 w0.102: 3.58,15.06 8.45,15.06 8.6,15.2 8.73,15.2
PR4D: length 6
  L6_SIG3 w0.089: v1(9.45,14.45) 9.2,14.7 8.76,14.7
  L6_SIG3 w0.102: 3.58,14.86 8.39,14.86 8.54,14.7 8.76,14.7
PR5A: length 5.4
  BOTTOM w0.102: 3.64,14.65 7.9,14.65 8.2,14.95 v1(8.95,14.95)
PR5B: length 7
  BOTTOM w0.089: v1(10.45,14.45) 10.2,14.2 8.26,14.2
  BOTTOM w0.102: 8.26,14.2 8.08,14.2 7.83,14.45 3.64,14.45
PR6C: length 6.9
  L4_SIGNAL2 w0.089: v1(9.95,14.45) 9.69,14.19 9.69,13.85 9.54,13.7 8.26,13.7
  L4_SIGNAL2 w0.102: 3.64,13.86 7.95,13.86 8.11,13.7 8.26,13.7
PR6D: length 5.5
  L4_SIGNAL2 w0.089: v1(8.95,14.45) 8.69,14.19 8.29,14.19
  L4_SIGNAL2 w0.102: 3.64,14.06 8.01,14.06 8.15,14.19 8.29,14.19
PR7A: length 8
  L3_SIGNAL1 w0.089: 8.54,14.88 8.72,14.7 9.05,14.7 9.55,14.7 10.05,14.7 10.55,14.7 10.7,14.55 10.7,14.2 v1(10.95,13.95)
  L3_SIGNAL1 w0.102: 3.58,15.02 8.4,15.02 8.54,14.88
PR7B: length 5.2
  L3_SIGNAL1 w0.102: v1(8.45,14.45) 8.45,14.69 8.32,14.82 3.58,14.82
PR7C: length 7
  L6_SIG3 w0.089: 8.23,13.76 8.29,13.7 10.2,13.7 v1(10.45,13.95)
  L6_SIG3 w0.102: 3.58,13.84 8.15,13.84 8.23,13.76
PR7D: length 6
  L6_SIG3 w0.089: v1(9.45,13.95) 9.2,14.2 8.31,14.2 8.23,14.12
  L6_SIG3 w0.102: 3.58,14.04 8.15,14.04 8.23,14.12
PR8A: length 6.5
  L3_SIGNAL1 w0.089: v1(9.95,13.95) 9.7,14.2 9.35,14.2 8.23,14.2
  L3_SIGNAL1 w0.102: 3.58,14.03 7.9,14.03 8.08,14.2 8.23,14.2
PR8B: length 5.5
  L3_SIGNAL1 w0.089: 8.3,13.7 8.7,13.7 v1(8.95,13.95)
  L3_SIGNAL1 w0.102: 8.3,13.7 8.08,13.7 7.95,13.83 3.58,13.83
PR8C: length 4.8
  BOTTOM w0.102: 3.64,13.9 8.18,13.9 8.24,13.95 v1(8.45,13.95)
PR8D: length 6.4
  BOTTOM w0.089: 8.24,13.7 9.7,13.7 v1(9.95,13.45)
  BOTTOM w0.102: 3.64,13.7 8.24,13.7
PR9A: length 7.4
  BOTTOM w0.089: v1(10.45,13.45) 10.21,13.21 10.21,12.8 10.1,12.69 8.29,12.69
  BOTTOM w0.102: 3.64,12.89 7.88,12.89 8.08,12.69 8.29,12.69
PR9B: length 5.5
  BOTTOM w0.089: v1(8.95,13.45) 8.7,13.2 8.23,13.2
  BOTTOM w0.102: 8.23,13.2 8.04,13.2 7.94,13.09 3.64,13.09
PR10C: length 6
  L3_SIGNAL1 w0.089: v1(9.45,13.45) 9.2,13.2 8.23,13.2
  L3_SIGNAL1 w0.102: 3.58,13.06 7.78,13.06 7.92,13.2 8.23,13.2
PR10D: length 5
  L3_SIGNAL1 w0.102: v1(8.45,13.45) 7.89,13.45 7.7,13.26 3.58,13.26
PR11A: length 7.3
  BOTTOM w0.089: 8.79,15.69 9.05,15.69 9.19,15.55 9.19,15.35 9.35,15.2 10.05,15.2 10.3,14.95 v1(10.45,14.95)
  BOTTOM w0.102: 3.64,15.57 8.51,15.57 8.63,15.69 8.79,15.69
PR11B: length 9.2
  BOTTOM w0.089: 8.62,15.28 8.7,15.2 9.05,15.2 9.2,15.05 9.2,14.85 9.35,14.7 10.55,14.7 10.7,14.55 10.7,13.2 v1(10.45,12.95)
  BOTTOM w0.102: 8.62,15.28 8.52,15.38 3.64,15.38
PR11C: length 6.4
  L4_SIGNAL2 w0.089: v1(9.95,12.95) 9.7,13.2 8.31,13.2
  L4_SIGNAL2 w0.102: 3.64,13.2 8.31,13.2
PR11D: length 4.8
  L4_SIGNAL2 w0.102: v1(8.45,12.95) 8.13,12.95 8.08,13 3.64,13
PR12A: length 6
  L6_SIG3 w0.089: v1(9.45,12.95) 9.2,12.7 8.26,12.7 8.17,12.79
  L6_SIG3 w0.102: 8.17,12.79 8.1,12.86 3.58,12.86
PR12B: length 5.5
  L6_SIG3 w0.089: 8.24,13.21 8.69,13.21 v1(8.95,12.95)
  L6_SIG3 w0.102: 8.24,13.21 8.18,13.21 8.03,13.06 3.58,13.06
PR15A: length 4.9
  L3_SIGNAL1 w0.102: v1(8.45,12.45) 8.04,12.45 7.99,12.5 3.58,12.5
PR15B: length 5.5
  L3_SIGNAL1 w0.089: 8.17,12.7 8.7,12.7 v1(8.95,12.45)
  L3_SIGNAL1 w0.102: 3.58,12.7 8.17,12.7
PR16A: length 6
  L4_SIGNAL2 w0.089: 8.23,12.2 9.2,12.2 v1(9.45,12.45)
  L4_SIGNAL2 w0.102: 8.23,12.2 8.1,12.2 7.95,12.35 3.64,12.35
PR16B: length 7
  L4_SIGNAL2 w0.089: v1(10.45,12.45) 10.2,12.7 8.26,12.7
  L4_SIGNAL2 w0.102: 8.26,12.7 8.11,12.7 7.95,12.55 3.64,12.55
PR16C: length 7.4
  L4_SIGNAL2 w0.089: v1(9.95,12.45) 9.7,12.2 9.7,11.35 9.55,11.2 8.61,11.2 8.29,11.2
  L4_SIGNAL2 w0.102: 8.29,11.2 8.05,11.2 7.9,11.34 3.64,11.34
PR16D: length 6
  L4_SIGNAL2 w0.089: v1(9.45,11.95) 9.2,11.7 8.29,11.7
  L4_SIGNAL2 w0.102: 8.29,11.7 8.08,11.7 7.91,11.54 3.64,11.54
PR17A: length 4.9
  L3_SIGNAL1 w0.102: 3.58,11.78 6.74,11.78 6.92,11.95 8.45,11.95 v1(8.45,11.95)
PR17B: length 5.6
  L3_SIGNAL1 w0.089: v1(8.95,11.95) 8.7,12.2 8.2,12.2
  L3_SIGNAL1 w0.102: 3.58,11.97 6.66,11.97 6.89,12.2 8.2,12.2
PR17C: length 7
  L6_SIG3 w0.089: 8.33,12.2 10.2,12.2 v1(10.45,11.95)
  L6_SIG3 w0.102: 8.33,12.2 8.11,12.2 7.98,12.08 3.58,12.08
PR17D: length 6.5
  L6_SIG3 w0.089: v1(9.95,11.95) 9.7,11.7 8.29,11.7
  L6_SIG3 w0.102: 3.58,11.88 7.9,11.88 8.08,11.7 8.29,11.7
PR18A: length 5
  L3_SIGNAL1 w0.102: v1(8.45,11.45) 8.04,11.45 7.99,11.5 7.09,11.5 6.78,11.2 3.58,11.2
PR18B: length 7.6
  L3_SIGNAL1 w0.089: 8.26,11.7 10.7,11.7 v1(10.95,11.45)
  L3_SIGNAL1 w0.102: 8.26,11.7 7,11.7 6.7,11.4 3.58,11.4
PR19C: length 6
  L6_SIG3 w0.089: v1(9.45,11.45) 9.2,11.2 8.3,11.2
  L6_SIG3 w0.102: 3.58,11.08 8.04,11.08 8.17,11.2 8.3,11.2
PR19D: length 7
  L6_SIG3 w0.089: v1(9.95,11.45) 9.7,11.2 9.7,10.85 9.55,10.7 8.26,10.7
  L6_SIG3 w0.102: 3.58,10.88 7.99,10.88 8.17,10.7 8.26,10.7
PR21A: length 5.6
  L3_SIGNAL1 w0.089: v1(8.95,11.45) 8.7,11.2 8.35,11.2
  L3_SIGNAL1 w0.102: 8.35,11.2 8.09,11.2 8.04,11.15 7.12,11.15 6.81,10.84 3.58,10.84
PR21B: length 5
  L3_SIGNAL1 w0.102: 3.58,10.64 6.89,10.64 7.2,10.95 8.04,10.95 8.14,10.95 8.14,10.95 8.45,10.95 v1(8.45,10.95)
PR21C: length 5.5
  L4_SIGNAL2 w0.089: v1(8.95,10.95) 8.7,10.7 8.29,10.7
  L4_SIGNAL2 w0.102: 3.64,10.55 7.99,10.55 8.14,10.7 8.29,10.7
PR21D: length 6.9
  L4_SIGNAL2 w0.089: 8.36,10.2 9.55,10.2 9.7,10.35 9.7,10.7 v1(9.95,10.95)
  L4_SIGNAL2 w0.102: 3.64,10.35 7.98,10.35 8.13,10.2 8.36,10.2
PR22A: length 7
  BOTTOM w0.089: v1(10.45,11.45) 10.2,11.7 8.26,11.7
  BOTTOM w0.102: 3.64,11.58 7.89,11.58 8.01,11.7 8.26,11.7
PR22B: length 7
  BOTTOM w0.089: 8.2,11.2 8.85,11.2 10.2,11.2 v1(10.45,10.95)
  BOTTOM w0.102: 3.64,11.38 7.89,11.38 8.07,11.2 8.2,11.2
PR22C: length 6
  BOTTOM w0.089: v1(9.45,10.95) 9.2,10.7 8.26,10.7
  BOTTOM w0.102: 3.64,10.58 7.83,10.58 7.95,10.7 8.26,10.7
PR22D: length 6
  BOTTOM w0.089: v1(9.45,10.45) 9.2,10.2 8.23,10.2
  BOTTOM w0.102: 8.23,10.2 7.95,10.2 7.77,10.38 3.64,10.38
PR23A: length 5.7
  L3_SIGNAL1 w0.089: 8.29,10.7 8.7,10.7 8.76,10.64 8.76,10.64 v1(8.95,10.45)
  L3_SIGNAL1 w0.102: 3.58,10.25 6.88,10.25 7.33,10.7 8.29,10.7
PR23B: length 5
  L3_SIGNAL1 w0.102: 3.58,10.05 6.96,10.05 7.36,10.45 8.45,10.45 v1(8.45,10.45)
PR23C: length 5.1
  L3_SIGNAL1 w0.102: v1(8.45,9.95) 8.45,9.95 8.2,9.95 8.15,10 7.66,10 7.11,9.45 3.58,9.45
PR23D: length 6.7
  L3_SIGNAL1 w0.089: v1(9.95,10.45) 9.83,10.33 9.82,10.33 9.7,10.2 8.23,10.2
  L3_SIGNAL1 w0.102: 8.23,10.2 7.58,10.2 7.02,9.65 3.58,9.65
PR24A: length 5.5
  L4_SIGNAL2 w0.089: v1(8.95,9.95) 8.7,9.7 8.24,9.7
  L4_SIGNAL2 w0.102: 3.64,9.54 8.08,9.54 8.24,9.7
PR24B: length 6.4
  L4_SIGNAL2 w0.089: 8.15,9.2 9.05,9.2 9.2,9.35 9.2,9.7 v1(9.45,9.95)
  L4_SIGNAL2 w0.102: 8.15,9.2 8.01,9.34 3.64,9.34
PR24C: length 6
  L6_SIG3 w0.089: 9.7,8.39 9.7,9.7 v1(9.95,9.95)
  L6_SIG3 w0.102: 9.7,8.39 9.7,8.22 9.85,8.08 9.85,4.08
PR24D: length 8.3
  L6_SIG3 w0.089: v1(11.45,11.45) 11.2,11.2 10.85,11.2 10.7,11.05 10.7,9.85 10.55,9.7 10.35,9.7 10.2,9.55 10.2,8.5
  L6_SIG3 w0.102: 10.2,8.5 10.2,8.5 10.2,8.23 10.04,8.08 10.04,4.08
PR25A: length 5.3
  L3_SIGNAL1 w0.102: v1(8.45,9.45) 8.45,9.45 7.97,9.45 6.85,8.33 3.58,8.33
PR25B: length 6
  L3_SIGNAL1 w0.089: 8.19,9.71 8.69,9.71 v1(8.95,9.45)
  L3_SIGNAL1 w0.102: 8.19,9.71 7.95,9.71 6.77,8.53 3.58,8.53
PR25C: length 7
  L6_SIG3 w0.089: 8.26,10.2 10.2,10.2 v1(10.45,10.45)
  L6_SIG3 w0.102: 3.58,10.06 7.96,10.06 8.11,10.2 8.26,10.2
PR25D: length 6
  L6_SIG3 w0.089: 8.23,9.7 9.2,9.7 v1(9.45,9.45)
  L6_SIG3 w0.102: 3.58,9.86 7.89,9.86 8.05,9.7 8.23,9.7
PT9A: length 6
  L3_SIGNAL1 w0.089: 16.55,16.2 16.2,16.2 v1(15.95,16.45)
  L3_SIGNAL1 w0.102: 21.82,16.2 16.55,16.2
PT9B: length 5.4
  L3_SIGNAL1 w0.102: v1(16.45,16.45) 16.73,16.45 16.78,16.4 21.82,16.4
PT9C: length 4.7
  L3_SIGNAL1 w0.102: 16.07,21.45 16.07,17.33 v1(16.45,16.95)
PT9D: length 5.2
  L3_SIGNAL1 w0.089: v1(15.45,16.45) 15.7,16.7 15.7,17.21
  L3_SIGNAL1 w0.102: 15.88,21.45 15.88,17.39 15.7,17.21
PT10A: length 6
  L3_SIGNAL1 w0.089: v1(15.95,15.95) 15.7,16.2 15.35,16.2 15.2,16.35 15.2,17.24
  L3_SIGNAL1 w0.102: 15.2,21.45 15.2,17.24
PT10B: length 4.5
  L3_SIGNAL1 w0.102: v1(15.45,16.95) 15.45,17.26 15.4,17.31 15.4,21.45
PT10C: length 5.7
  L6_SIG3 w0.089: v1(14.95,15.95) 14.95,16.1 15.2,16.35 15.2,17.17
  L6_SIG3 w0.102: 15.2,17.17 15.38,17.34 15.38,21.45
PT10D: length 4.7
  L6_SIG3 w0.102: v1(15.95,16.95) 15.57,17.33 15.57,21.45
PT11A: length 9.9
  L4_SIGNAL2 w0.089: 16.57,16.2 14.85,16.2 14.7,16.05 14.7,14.85 14.55,14.7 13.7,14.7 v1(13.45,14.45)
  L4_SIGNAL2 w0.102: 21.82,16.04 16.98,16.04 16.82,16.2 16.57,16.2
PT11B: length 6.5
  L4_SIGNAL2 w0.089: v1(15.45,15.95) 15.51,15.89 15.51,15.87 15.69,15.7 16.54,15.7
  L4_SIGNAL2 w0.102: 16.54,15.7 16.82,15.7 16.97,15.84 21.82,15.84
PT11C: length 6.7
  L4_SIGNAL2 w0.089: 14.2,17.17 14.2,15.2 v1(14.45,14.95)
  L4_SIGNAL2 w0.102: 14.2,17.17 14.2,17.32 14.35,17.48 14.35,21.45
PT11D: length 5.2
  L4_SIGNAL2 w0.089: v1(14.95,16.45) 14.7,16.7 14.7,17.2
  L4_SIGNAL2 w0.102: 14.55,21.45 14.55,17.45 14.7,17.3 14.7,17.2
PT12A: length 6.1
  L3_SIGNAL1 w0.089: 14.7,17.05 14.7,15.7 v1(14.45,15.45)
  L3_SIGNAL1 w0.102: 14.7,21.45 14.7,17.05
PT12B: length 4.5
  L3_SIGNAL1 w0.102: v1(14.95,16.95) 14.95,17.26 14.9,17.31 14.9,21.45
PT12C: length 6.5
  BOTTOM w0.089: v1(15.45,15.45) 15.7,15.7 16.67,15.7
  BOTTOM w0.102: 21.82,15.7 16.67,15.7
PT13A: length 9
  BOTTOM w0.089: v1(13.45,13.95) 13.2,14.2 13.2,15.55 13.35,15.7 14.58,15.7 14.7,15.82 14.7,17.07
  BOTTOM w0.102: 14.85,21.45 14.85,17.47 14.7,17.32 14.7,17.07
PT13B: length 6.2
  BOTTOM w0.089: 15.2,17.11 15.2,15.7 v1(14.95,15.45)
  BOTTOM w0.102: 15.04,21.45 15.04,17.45 15.2,17.29 15.2,17.11
PT14A: length 4.5
  L3_SIGNAL1 w0.102: 14.4,21.45 14.4,17.31 14.45,17.26 v1(14.45,16.95)
PT14B: length 6.1
  L3_SIGNAL1 w0.089: 14.2,17.17 14.2,15.7 v1(13.95,15.45)
  L3_SIGNAL1 w0.102: 14.2,21.45 14.2,17.17
PT14C: length 5.2
  L6_SIG3 w0.089: v1(14.45,16.45) 14.2,16.7 14.2,17.07
  L6_SIG3 w0.102: 14.34,21.45 14.34,17.42 14.2,17.27 14.2,17.07
PT14D: length 8.3
  L6_SIG3 w0.089: 14.7,17.1 14.7,16.35 14.55,16.2 13.85,16.2 13.7,16.05 13.7,15.85 13.55,15.7 13.35,15.7 13.2,15.55 13.2,15.51 13.2,14.7 v1(12.95,14.45)
  L6_SIG3 w0.102: 14.54,21.45 14.54,17.42 14.7,17.26 14.7,17.1
PT15A: length 5.7
  BOTTOM w0.089: 14.1,17.25 14.21,17.14 14.21,16.19 v1(14.45,15.95)
  BOTTOM w0.102: 14.04,21.45 14.04,17.3 14.1,17.25
PT15B: length 5.7
  BOTTOM w0.089: 13.8,17.27 13.71,17.17 13.71,16.19 v1(13.95,15.95)
  BOTTOM w0.102: 13.85,21.45 13.85,17.31 13.8,17.27
PT16A: length 6.6
  L3_SIGNAL1 w0.089: v1(13.95,14.95) 13.7,15.2 13.7,17.05
  L3_SIGNAL1 w0.102: 13.7,21.45 13.7,17.05
PT16B: length 4.5
  L3_SIGNAL1 w0.102: v1(13.95,16.95) 13.95,17.26 13.9,17.31 13.9,21.45
PT16C: length 8.5
  BOTTOM w0.089: 16.64,15.2 13.7,15.2 v1(13.45,14.95)
  BOTTOM w0.102: 21.82,15.2 16.64,15.2
PT17A: length 7.2
  BOTTOM w0.089: v1(12.45,14.45) 12.7,14.7 12.7,17.14
  BOTTOM w0.102: 12.7,17.14 12.7,17.29 12.86,17.45 12.86,21.45
PT17B: length 5.7
  BOTTOM w0.089: 13.2,17.11 13.2,16.2 v1(13.45,15.95)
  BOTTOM w0.102: 13.05,21.45 13.05,17.47 13.2,17.32 13.2,17.11
PT17C: length 7.7
  L4_SIGNAL2 w0.089: v1(12.95,13.95) 13.2,14.2 13.2,17.17
  L4_SIGNAL2 w0.102: 13.2,17.17 13.2,17.29 13.36,17.45 13.36,21.45
PT17D: length 5.2
  L4_SIGNAL2 w0.089: 13.69,17.07 13.69,16.71 v1(13.95,16.45)
  L4_SIGNAL2 w0.102: 13.55,21.45 13.55,17.41 13.69,17.27 13.69,17.07
PT18A: length 7
  L6_SIG3 w0.089: v1(12.95,14.95) 12.7,15.2 12.7,15.55 12.85,15.7 13.05,15.7 13.2,15.85 13.2,16.99
  L6_SIG3 w0.102: 13.2,16.99 13.2,17.27 13.35,17.42 13.35,21.45
PT18B: length 5.2
  L6_SIG3 w0.089: v1(13.45,16.45) 13.7,16.7 13.7,17.07
  L6_SIG3 w0.102: 13.7,17.07 13.7,17.23 13.54,17.39 13.54,21.45
PT18C: length 9.5
  L6_SIG3 w0.089: v1(13.45,15.45) 13.7,15.2 14.05,15.2 14.2,15.35 14.2,15.55 14.35,15.7 15.07,15.7 15.2,15.83 15.2,16.05 15.35,16.2 15.55,16.2 15.7,16.35 15.7,16.55 15.85,16.7 16.71,16.7 16.83,16.58
  L6_SIG3 w0.102: 16.83,16.58 16.89,16.52 21.82,16.52
PT18D: length 11
  L6_SIG3 w0.089: v1(12.45,13.95) 12.7,14.2 13.55,14.2 13.7,14.35 13.7,14.55 13.85,14.7 14.08,14.7 14.2,14.82 14.2,15.05 14.35,15.2 15.57,15.2 15.7,15.33 15.7,16.05 15.84,16.19 15.85,16.2 16.76,16.2 16.79,16.23
  L6_SIG3 w0.102: 16.79,16.23 16.89,16.32 21.82,16.32
PT21A: length 5.2
  L6_SIG3 w0.089: 12.7,17.11 12.7,16.7 v1(12.95,16.45)
  L6_SIG3 w0.102: 12.7,17.11 12.7,17.29 12.57,17.42 12.57,21.45
PT21B: length 6.1
  L6_SIG3 w0.089: v1(12.95,15.95) 12.7,16.2 12.51,16.2 12.35,16.2 12.2,16.35 12.2,17.04
  L6_SIG3 w0.102: 12.37,21.45 12.37,17.37 12.2,17.2 12.2,17.04
PT21C: length 4.5
  L3_SIGNAL1 w0.102: v1(13.45,16.95) 13.45,17.29 13.4,17.34 13.4,21.45
PT21D: length 6.1
  L3_SIGNAL1 w0.089: v1(12.95,15.45) 13.2,15.7 13.2,17.05
  L3_SIGNAL1 w0.102: 13.2,21.45 13.2,17.05
PT22A: length 4.5
  L3_SIGNAL1 w0.102: 12.9,21.45 12.9,17.34 12.95,17.29 v1(12.95,16.95)
PT22B: length 6.1
  L3_SIGNAL1 w0.089: v1(12.45,15.45) 12.7,15.7 12.7,17.09
  L3_SIGNAL1 w0.102: 12.7,21.45 12.7,17.09
PT22C: length 4.5
  L3_SIGNAL1 w0.102: v1(12.45,16.95) 12.45,17.32 12.4,17.38 12.4,21.45
PT22D: length 5.1
  L3_SIGNAL1 w0.089: 12.2,17.23 12.2,16.7 v1(12.45,16.45)
  L3_SIGNAL1 w0.102: 12.2,21.45 12.2,17.23
PT25A: length 5.7
  L4_SIGNAL2 w0.089: 12.2,17.07 12.2,16.2 v1(12.45,15.95)
  L4_SIGNAL2 w0.102: 12.39,21.45 12.39,17.39 12.2,17.2 12.2,17.07
PT25B: length 6.6
  L4_SIGNAL2 w0.089: v1(12.45,14.95) 12.7,15.2 12.7,17.07
  L4_SIGNAL2 w0.102: 12.59,21.45 12.59,17.39 12.7,17.28 12.7,17.07
PT25C: length 5.1
  L3_SIGNAL1 w0.089: 11.7,17.05 11.7,16.7 v1(11.95,16.45)
  L3_SIGNAL1 w0.102: 11.7,21.45 11.7,17.05
PT25D: length 4.5
  L3_SIGNAL1 w0.102: 11.9,21.45 11.9,17.38 11.95,17.32 v1(11.95,16.95)
PT26A: length 6.2
  L6_SIG3 w0.089: v1(11.95,15.45) 11.7,15.7 11.7,17.03
  L6_SIG3 w0.102: 11.7,17.03 11.7,17.22 11.56,17.36 11.56,21.45
PT26B: length 7.5
  L6_SIG3 w0.089: v1(11.95,14.45) 11.7,14.7 11.7,15.05 11.55,15.2 11.35,15.2 11.2,15.35 11.2,16.67 11.2,17.07
  L6_SIG3 w0.102: 11.2,17.07 11.2,17.19 11.36,17.35 11.36,21.45
PT26C: length 5.7
  L4_SIGNAL2 w0.089: 11.7,17.12 11.7,16.2 v1(11.95,15.95)
  L4_SIGNAL2 w0.102: 11.7,17.12 11.7,17.32 11.58,17.45 11.58,21.45
PT26D: length 7.1
  L4_SIGNAL2 w0.089: 11.2,17.11 11.2,15.35 11.35,15.2 11.7,15.2 v1(11.95,14.95)
  L4_SIGNAL2 w0.102: 11.2,17.11 11.2,17.26 11.38,17.44 11.38,21.45
PT27A: length 5.9
  BOTTOM w0.089: v1(11.45,15.95) 11.2,16.2 11.2,17.04 11.19,17.05 11.19,17.05 10.99,17.26
  BOTTOM w0.102: 10.54,21.45 10.54,17.7 10.99,17.26
PT27B: length 5.4
  BOTTOM w0.102: v1(9.45,16.45) 9.45,16.8 10.34,17.7 10.34,21.45
PT27C: length 4.5
  L3_SIGNAL1 w0.102: v1(11.45,16.95) 11.45,17.36 11.4,17.4 11.4,21.45
PT27D: length 5.1
  L3_SIGNAL1 w0.089: v1(11.45,16.45) 11.21,16.69 11.21,17.05
  L3_SIGNAL1 w0.102: 11.21,21.45 11.21,17.05
PT28A: length 4.5
  L3_SIGNAL1 w0.102: v1(10.95,16.95) 10.95,17.32 10.9,17.38 10.9,20.73 10.89,20.74 10.89,21.45
PT28B: length 6.9
  L3_SIGNAL1 w0.089: 10.69,17.16 10.69,15.85 10.85,15.7 11.05,15.7 11.2,15.55 11.2,15.2 v1(11.45,14.95)
  L3_SIGNAL1 w0.102: 10.69,17.16 10.69,20.73 10.7,20.74 10.7,21.45
PT32A: length 8.7
  BOTTOM w0.089: 8.79,16.26 8.85,16.2 9.05,16.2 9.2,16.05 9.2,15.85 9.35,15.7 10.05,15.7 10.2,15.55 10.2,15.35 10.35,15.2 11.2,15.2 v1(11.45,15.45)
  BOTTOM w0.102: 8.85,21.45 8.85,16.81 8.7,16.67 8.7,16.35 8.79,16.26
